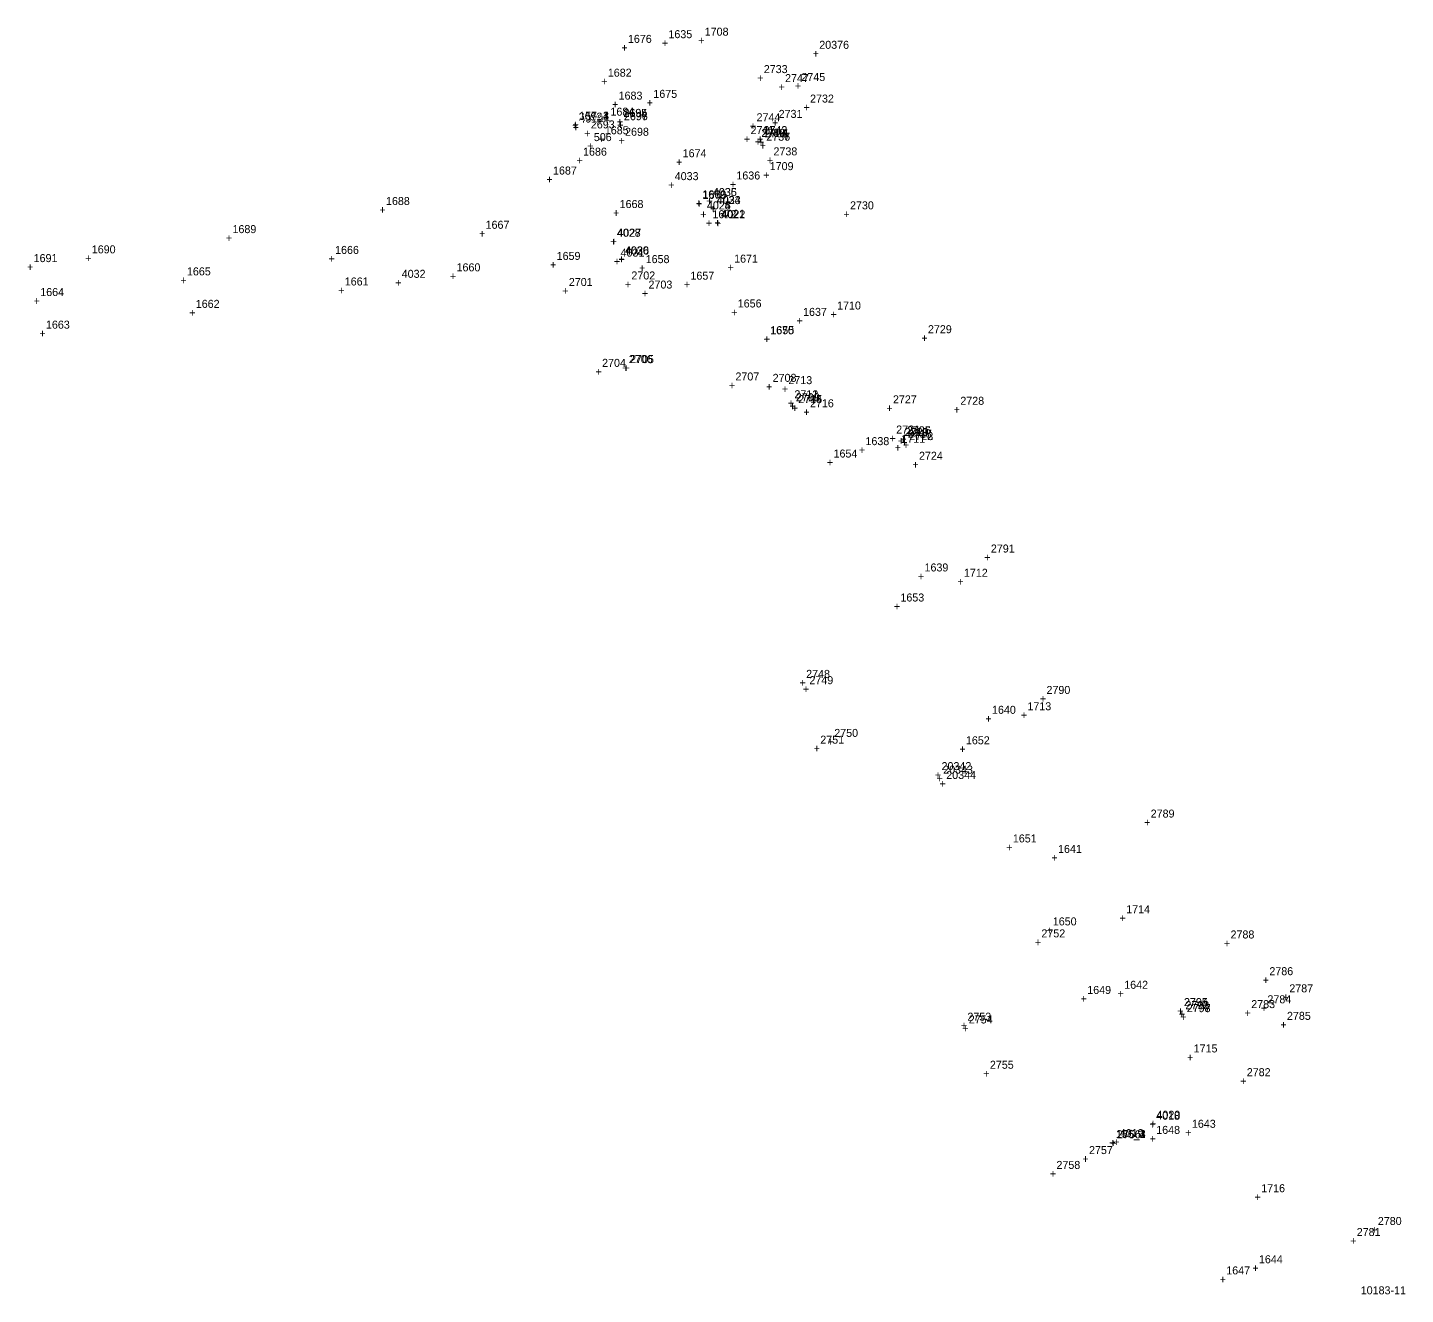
# Model space of a CAD drawing. Extents: x 1036751 to 1042192, y 772604 to 785439.
# Drawn here: x 1039355.7 to 1039786.2, y 776201.3 to 776597 of the extents above; entities that cross this region are included whole.
import ezdxf

# ---------------------------------------------------------------- set-up
doc = ezdxf.new("R2010")
doc.units = 0
for name, color, linetype in [('S_Buildings', 7, 'Continuous'), ('S_Buildings_SillElevation', 7, 'Continuous'), ('S_Control_Geodetic_ControlPoint', 7, 'Continuous'), ('S_Control_Temp_Traverse', 7, 'Continuous'), ('S_Control_Traverse_Point', 7, 'Continuous'), ('S_Drainage_CB', 7, 'Continuous'), ('S_Drainage_Culvert_Top', 7, 'Continuous'), ('S_Drainage_Invert', 7, 'Continuous'), ('S_Drainage_Sump', 7, 'Continuous'), ('S_Ground_LevelString', 7, 'Continuous'), ('S_Property_ElectricalOutlet', 7, 'Continuous'), ('S_Property_IronPipeFound', 7, 'Continuous'), ('S_Property_Mailbox', 7, 'Continuous'), ('S_Property_Well_Top', 7, 'Continuous'), ('S_Roadway_Centerline', 7, 'Continuous'), ('S_Roadway_Edge_Pavement', 7, 'Continuous'), ('S_Traffic_JunctionBox', 7, 'Continuous'), ('S_Traffic_Post_Conc', 7, 'Continuous'), ('S_Traffic_Sign_DoublePost', 7, 'Continuous'), ('S_Traffic_Sign_SinglePost', 7, 'Continuous'), ('S_Trees_Conifer_Pay', 7, 'Continuous'), ('S_Trees_Decid_Pay', 7, 'Continuous'), ('S_Trees_Stump', 7, 'Continuous'), ('S_Utilities_GuyWire3', 7, 'Continuous'), ('S_Utilities_Hydrant', 7, 'Continuous'), ('S_Utilities_Pole_Power', 7, 'Continuous'), ('S_Utilities_UG_Sanitary_MH', 7, 'Continuous'), ('S_Utilities_UG_Sanitary_Sewer', 7, 'Continuous'), ('S_Utilities_UG_Water_Gate', 7, 'Continuous'), ('S_Utilities_UG_Water_Line', 7, 'Continuous')]:
    doc.layers.add(name, color=color, linetype=linetype)

msp = doc.modelspace()

# ---------------------------------------------------------------- texts
at = {"layer": 'S_Buildings'}
for s, p in [('2704', (1039535.21, 776491.05)), ('+', (1039541.9, 776489.46)), ('2705', (1039543.96, 776492.21)), ('+', (1039533.15, 776488.3)), ('+', (1039596.9, 776391.15)), ('2748', (1039598.96, 776393.9)), ('2751', (1039603.37, 776373.35)), ('2750', (1039607.73, 776375.46)), ('+', (1039601.31, 776370.6)), ('+', (1039605.67, 776372.71)), ('2753', (1039649.32, 776286.82)), ('+', (1039647.26, 776284.07)), ('2755', (1039656.35, 776271.82)), ('+', (1039654.29, 776269.07))]:
    msp.add_text(s, height=2.5, dxfattribs=at).set_placement(p)
at = {"layer": 'S_Buildings_SillElevation'}
for s, p in [('+', (1039541.51, 776489.48)), ('2706', (1039543.57, 776492.23)), ('2749', (1039599.97, 776391.93)), ('+', (1039597.9, 776389.18)), ('+', (1039647.7, 776283.22)), ('2754', (1039649.76, 776285.97))]:
    msp.add_text(s, height=2.5, dxfattribs=at).set_placement(p)
at = {"layer": 'S_Control_Geodetic_ControlPoint'}
msp.add_text('10183-11', height=2.5, dxfattribs=at).set_placement((1039772.19, 776201.36))
msp.add_text('10183-11', height=2.5, dxfattribs=at).set_placement((1039772.19, 776201.36))
msp.add_text('10183-11', height=2.5, dxfattribs=at).set_placement((1039772.19, 776201.36))
msp.add_text('10183-11', height=2.5, dxfattribs=at).set_placement((1039772.19, 776201.36))
msp.add_text('10183-11', height=2.5, dxfattribs=at).set_placement((1039772.19, 776201.36))
msp.add_text('10183-11', height=2.5, dxfattribs=at).set_placement((1039772.19, 776201.36))
at = {"layer": 'S_Control_Temp_Traverse'}
for s, p in [('157_3', (1039528.05, 776568.25)), ('157_2', (1039528.05, 776568.25)), ('157', (1039528.05, 776568.25)), ('157', (1039528.05, 776568.25)), ('157_1', (1039528.05, 776568.25)), ('157_4', (1039528.05, 776568.25)), ('+', (1039525.99, 776565.5)), ('+', (1039525.99, 776565.5)), ('+', (1039525.99, 776565.5)), ('+', (1039525.99, 776565.5)), ('+', (1039525.99, 776565.5)), ('+', (1039525.99, 776565.5)), ('156', (1039695.7, 776250.22)), ('156_1', (1039695.7, 776250.22)), ('156_3', (1039695.7, 776250.22)), ('156_2', (1039695.7, 776250.22)), ('156_4', (1039695.7, 776250.22)), ('+', (1039693.64, 776247.47)), ('+', (1039693.64, 776247.47)), ('+', (1039693.64, 776247.47)), ('+', (1039693.64, 776247.47)), ('+', (1039693.64, 776247.47))]:
    msp.add_text(s, height=2.5, dxfattribs=at).set_placement(p)
at = {"layer": 'S_Control_Traverse_Point'}
for s, p in [('+', (1039530.56, 776558.82)), ('+', (1039530.56, 776558.82)), ('+', (1039530.56, 776558.82)), ('+', (1039530.56, 776558.82)), ('+', (1039530.56, 776558.82)), ('+', (1039530.56, 776558.82)), ('+', (1039530.56, 776558.82)), ('+', (1039530.56, 776558.82)), ('506', (1039532.62, 776561.57)), ('506', (1039532.62, 776561.57)), ('506', (1039532.62, 776561.57)), ('506', (1039532.62, 776561.57)), ('506', (1039532.62, 776561.57)), ('506', (1039532.62, 776561.57)), ('506', (1039532.62, 776561.57)), ('506', (1039532.62, 776561.57))]:
    msp.add_text(s, height=2.5, dxfattribs=at).set_placement(p)
at = {"layer": 'S_Drainage_CB'}
for s, p in [('2694', (1039541.93, 776569.13)), ('+', (1039539.86, 776566.38)), ('2734', (1039585.92, 776562.75)), ('+', (1039583.86, 776560)), ('2709', (1039595.76, 776480.33)), ('+', (1039593.7, 776477.58)), ('2717', (1039630.77, 776468.96)), ('+', (1039628.71, 776466.21)), ('+', (1039715.34, 776287.68)), ('2792', (1039717.4, 776290.43))]:
    msp.add_text(s, height=2.5, dxfattribs=at).set_placement(p)
at = {"layer": 'S_Drainage_Culvert_Top'}
for s, p in [('2697', (1039542.02, 776568.08)), ('2744', (1039583.46, 776567.76)), ('+', (1039539.96, 776565.33)), ('2698', (1039542.39, 776563.23)), ('+', (1039581.4, 776565.01)), ('2741', (1039581.58, 776563.73)), ('2740', (1039585, 776562.89)), ('2743', (1039585.66, 776563.7)), ('+', (1039540.33, 776560.48)), ('+', (1039579.52, 776560.98)), ('+', (1039582.93, 776560.14)), ('+', (1039583.6, 776560.95)), ('+', (1039584.44, 776558.92)), ('2737', (1039586.5, 776561.67)), ('+', (1039586.69, 776554.35)), ('2738', (1039588.75, 776557.1)), ('2713', (1039593.4, 776485.65)), ('+', (1039591.34, 776482.9)), ('2712', (1039595.28, 776481.23)), ('+', (1039593.22, 776478.48)), ('+', (1039594.47, 776476.97)), ('2715', (1039596.53, 776479.72)), ('2716', (1039600.15, 776478.42)), ('+', (1039624.01, 776476.9)), ('2727', (1039626.07, 776479.65)), ('+', (1039598.09, 776475.67)), ('2721', (1039627.08, 776470.22)), ('2720', (1039629.73, 776469.44)), ('2726', (1039630.41, 776469.99)), ('2723', (1039631.21, 776468.17)), ('+', (1039625.02, 776467.47)), ('+', (1039627.67, 776466.69)), ('+', (1039628.35, 776467.24)), ('+', (1039629.15, 776465.42)), ('+', (1039632.14, 776459.28)), ('2724', (1039634.2, 776462.03)), ('2795', (1039716.96, 776291.39)), ('+', (1039714.89, 776288.64)), ('2798', (1039717.83, 776289.5)), ('+', (1039715.77, 776286.75))]:
    msp.add_text(s, height=2.5, dxfattribs=at).set_placement(p)
at = {"layer": 'S_Drainage_Invert'}
for s, p in [('2696', (1039542.04, 776568.11)), ('+', (1039539.98, 776565.36)), ('2739', (1039584.96, 776562.9)), ('2742', (1039585.63, 776563.74)), ('+', (1039582.9, 776560.15)), ('+', (1039583.57, 776560.99)), ('+', (1039584.45, 776558.94)), ('2736', (1039586.51, 776561.69)), ('2711', (1039595.28, 776481.25)), ('+', (1039593.22, 776478.5)), ('+', (1039594.43, 776476.96)), ('2714', (1039596.49, 776479.71)), ('2719', (1039629.69, 776469.46)), ('2725', (1039630.44, 776469.97)), ('2722', (1039631.21, 776468.17)), ('+', (1039627.63, 776466.71)), ('+', (1039628.38, 776467.22)), ('+', (1039629.15, 776465.42)), ('2794', (1039716.99, 776291.38)), ('+', (1039714.93, 776288.63)), ('2797', (1039717.87, 776289.5)), ('+', (1039715.8, 776286.75))]:
    msp.add_text(s, height=2.5, dxfattribs=at).set_placement(p)
at = {"layer": 'S_Drainage_Sump'}
for s, p in [('2695', (1039541.85, 776569.12)), ('+', (1039539.79, 776566.37)), ('2735', (1039585.92, 776562.73)), ('+', (1039583.86, 776559.98)), ('+', (1039593.7, 776477.5)), ('2710', (1039595.76, 776480.25)), ('2718', (1039630.71, 776468.91)), ('+', (1039628.65, 776466.16)), ('+', (1039715.36, 776287.67)), ('2793', (1039717.42, 776290.42))]:
    msp.add_text(s, height=2.5, dxfattribs=at).set_placement(p)
at = {"layer": 'S_Ground_LevelString'}
for s, p in [('1676', (1039543.28, 776592.24)), ('+', (1039541.22, 776589.49)), ('1675', (1039551.22, 776575.07)), ('+', (1039549.16, 776572.32)), ('1674', (1039560.38, 776556.52)), ('+', (1039558.32, 776553.77)), ('1673', (1039566.61, 776543.51)), ('+', (1039564.55, 776540.76)), ('1672', (1039569.68, 776537.47)), ('+', (1039567.62, 776534.72)), ('1671', (1039576.46, 776523.59)), ('+', (1039574.4, 776520.84)), ('+', (1039585.64, 776498.46)), ('1670', (1039587.7, 776501.21))]:
    msp.add_text(s, height=2.5, dxfattribs=at).set_placement(p)
at = {"layer": 'S_Property_ElectricalOutlet'}
for s, p in [('2786', (1039743.65, 776301.04)), ('+', (1039741.58, 776298.29)), ('2785', (1039749.14, 776287.09)), ('+', (1039747.08, 776284.34))]:
    msp.add_text(s, height=2.5, dxfattribs=at).set_placement(p)
at = {"layer": 'S_Property_IronPipeFound'}
for s, p in [('2747', (1039592.37, 776579.98)), ('+', (1039590.3, 776577.23)), ('+', (1039704.52, 776347.52)), ('2789', (1039706.58, 776350.27))]:
    msp.add_text(s, height=2.5, dxfattribs=at).set_placement(p)
at = {"layer": 'S_Property_Mailbox'}
for s, p in [('+', (1039671.97, 776386.13)), ('2790', (1039674.03, 776388.88)), ('2752', (1039672.44, 776312.85)), ('+', (1039670.38, 776310.1))]:
    msp.add_text(s, height=2.5, dxfattribs=at).set_placement(p)
at = {"layer": 'S_Property_Well_Top'}
for s, p in [('2788', (1039731.52, 776312.51)), ('+', (1039729.45, 776309.76))]:
    msp.add_text(s, height=2.5, dxfattribs=at).set_placement(p)
at = {"layer": 'S_Roadway_Centerline'}
for s, p in [('1635', (1039555.93, 776593.71)), ('+', (1039553.87, 776590.96)), ('1636', (1039577.16, 776549.57)), ('+', (1039575.1, 776546.82)), ('1668', (1039540.69, 776540.65)), ('1669', (1039566.52, 776543.69)), ('+', (1039538.63, 776537.9)), ('+', (1039564.46, 776540.94)), ('1667', (1039498.82, 776534.18)), ('+', (1039496.76, 776531.43)), ('1666', (1039451.81, 776526.32)), ('1665', (1039405.53, 776519.62)), ('+', (1039449.75, 776523.57)), ('+', (1039403.46, 776516.87)), ('1664', (1039359.71, 776513.16)), ('+', (1039357.65, 776510.41)), ('1637', (1039597.99, 776506.97)), ('+', (1039595.93, 776504.22)), ('+', (1039615.42, 776463.85)), ('1638', (1039617.48, 776466.6)), ('1639', (1039635.93, 776427.15)), ('+', (1039633.87, 776424.4)), ('1640', (1039657.01, 776382.68)), ('+', (1039654.95, 776379.93)), ('1641', (1039677.63, 776339.22)), ('+', (1039675.57, 776336.47)), ('1642', (1039698.31, 776296.79)), ('+', (1039696.24, 776294.04)), ('1643', (1039719.45, 776253.38)), ('+', (1039717.39, 776250.63)), ('1644', (1039740.39, 776211.07)), ('+', (1039738.33, 776208.32))]:
    msp.add_text(s, height=2.5, dxfattribs=at).set_placement(p)
at = {"layer": 'S_Roadway_Edge_Pavement'}
for s, p in [('1708', (1039567.27, 776594.49)), ('+', (1039565.21, 776591.74)), ('1682', (1039537, 776581.68)), ('+', (1039534.94, 776578.93)), ('+', (1039538.31, 776571.77)), ('1683', (1039540.37, 776574.52)), ('1684', (1039537.82, 776569.5)), ('+', (1039535.76, 776566.75)), ('1685', (1039536.06, 776563.7)), ('+', (1039534, 776560.95)), ('+', (1039527.2, 776554.26)), ('1686', (1039529.26, 776557.01)), ('1687', (1039519.88, 776551.12)), ('+', (1039585.51, 776549.74)), ('1709', (1039587.57, 776552.49)), ('+', (1039517.82, 776548.37)), ('1688', (1039467.71, 776541.6)), ('+', (1039465.65, 776538.85)), ('1689', (1039419.76, 776532.82)), ('+', (1039417.69, 776530.07)), ('1691', (1039357.64, 776523.77)), ('1690', (1039375.81, 776526.5)), ('1659', (1039521.02, 776524.45)), ('1658', (1039548.83, 776523.45)), ('+', (1039355.58, 776521.02)), ('+', (1039373.75, 776523.75)), ('1660', (1039489.75, 776520.88)), ('+', (1039518.96, 776521.7)), ('+', (1039546.76, 776520.7)), ('1661', (1039454.83, 776516.47)), ('+', (1039487.69, 776518.13)), ('+', (1039560.75, 776515.53)), ('1657', (1039562.81, 776518.28)), ('+', (1039452.77, 776513.72)), ('+', (1039406.22, 776506.73)), ('1662', (1039408.29, 776509.48)), ('+', (1039575.53, 776506.85)), ('1656', (1039577.59, 776509.6)), ('1710', (1039608.62, 776508.96)), ('1663', (1039361.49, 776502.98)), ('+', (1039606.56, 776506.21)), ('+', (1039359.43, 776500.23)), ('+', (1039585.73, 776498.51)), ('1655', (1039587.79, 776501.26)), ('+', (1039626.63, 776464.58)), ('1711', (1039628.69, 776467.33)), ('+', (1039605.45, 776459.97)), ('1654', (1039607.51, 776462.72)), ('1712', (1039648.23, 776425.48)), ('+', (1039646.17, 776422.74)), ('1653', (1039628.4, 776417.76)), ('+', (1039626.34, 776415.01)), ('1713', (1039668.07, 776383.79)), ('+', (1039666.01, 776381.04)), ('1652', (1039648.86, 776373.16)), ('+', (1039646.8, 776370.41)), ('+', (1039661.45, 776339.76)), ('1651', (1039663.52, 776342.51)), ('+', (1039696.86, 776317.64)), ('1714', (1039698.93, 776320.39)), ('+', (1039673.94, 776313.84)), ('1650', (1039676, 776316.59)), ('+', (1039684.7, 776292.43)), ('1649', (1039686.76, 776295.18)), ('+', (1039717.93, 776274.17)), ('1715', (1039719.99, 776276.92)), ('+', (1039706.25, 776248.72)), ('1648', (1039708.31, 776251.47)), ('1716', (1039741.1, 776233.25)), ('+', (1039739.04, 776230.5)), ('1647', (1039730.18, 776207.58)), ('+', (1039728.12, 776204.83))]:
    msp.add_text(s, height=2.5, dxfattribs=at).set_placement(p)
at = {"layer": 'S_Traffic_JunctionBox'}
for s, p in [('2745', (1039597.47, 776580.33)), ('+', (1039595.41, 776577.58))]:
    msp.add_text(s, height=2.5, dxfattribs=at).set_placement(p)
at = {"layer": 'S_Traffic_Post_Conc'}
for s, p in [('2707', (1039576.86, 776486.8)), ('+', (1039574.8, 776484.05))]:
    msp.add_text(s, height=2.5, dxfattribs=at).set_placement(p)
at = {"layer": 'S_Traffic_Sign_DoublePost'}
for s, p in [('2784', (1039743.05, 776292.27)), ('+', (1039735.92, 776288.01)), ('2783', (1039737.98, 776290.76)), ('+', (1039740.98, 776289.52)), ('2780', (1039777.53, 776223.02)), ('2781', (1039770.94, 776219.57)), ('+', (1039775.47, 776220.27)), ('+', (1039768.88, 776216.82))]:
    msp.add_text(s, height=2.5, dxfattribs=at).set_placement(p)
at = {"layer": 'S_Traffic_Sign_SinglePost'}
for s, p in [('+', (1039529.64, 776562.77)), ('2693', (1039531.7, 776565.52)), ('+', (1039542.3, 776515.6)), ('2702', (1039544.36, 776518.35))]:
    msp.add_text(s, height=2.5, dxfattribs=at).set_placement(p)
at = {"layer": 'S_Trees_Conifer_Pay'}
for s, p in [('2787', (1039749.88, 776295.68)), ('+', (1039747.82, 776292.93))]:
    msp.add_text(s, height=2.5, dxfattribs=at).set_placement(p)
at = {"layer": 'S_Trees_Decid_Pay'}
for s, p in [('2701', (1039524.82, 776516.3)), ('2703', (1039549.71, 776515.5)), ('+', (1039522.76, 776513.55)), ('+', (1039547.65, 776512.75)), ('+', (1039634.94, 776498.81)), ('2729', (1039637, 776501.56)), ('2708', (1039588.49, 776486.37)), ('+', (1039586.43, 776483.62)), ('+', (1039645.05, 776476.45)), ('2728', (1039647.11, 776479.2))]:
    msp.add_text(s, height=2.5, dxfattribs=at).set_placement(p)
at = {"layer": 'S_Trees_Stump'}
for s, p in [('+', (1039610.6, 776537.5)), ('2730', (1039612.66, 776540.25))]:
    msp.add_text(s, height=2.5, dxfattribs=at).set_placement(p)
at = {"layer": 'S_Utilities_GuyWire3'}
for s, p in [('+', (1039583.66, 776580.05)), ('2733', (1039585.72, 776582.8)), ('2732', (1039600.18, 776573.6)), ('+', (1039598.12, 776570.85)), ('2758', (1039677.14, 776240.53)), ('+', (1039675.08, 776237.78))]:
    msp.add_text(s, height=2.5, dxfattribs=at).set_placement(p)
at = {"layer": 'S_Utilities_Hydrant'}
for s, p in [('2692', (1039527.87, 776567.94)), ('+', (1039525.81, 776565.19)), ('2756', (1039696.01, 776250.09)), ('+', (1039693.95, 776247.34))]:
    msp.add_text(s, height=2.5, dxfattribs=at).set_placement(p)
at = {"layer": 'S_Utilities_Pole_Power'}
for s, p in [('2731', (1039590.36, 776568.81)), ('+', (1039588.29, 776566.06)), ('2791', (1039656.66, 776433.06)), ('+', (1039654.6, 776430.31)), ('2782', (1039736.59, 776269.5)), ('+', (1039734.53, 776266.75)), ('2757', (1039687.31, 776245.17)), ('+', (1039685.24, 776242.42))]:
    msp.add_text(s, height=2.5, dxfattribs=at).set_placement(p)
at = {"layer": 'S_Utilities_UG_Sanitary_MH'}
for s, p in [('20376', (1039603.05, 776590.39)), ('+', (1039600.99, 776587.64)), ('20342', (1039641.25, 776365.09)), ('+', (1039639.18, 776362.34))]:
    msp.add_text(s, height=2.5, dxfattribs=at).set_placement(p)
at = {"layer": 'S_Utilities_UG_Sanitary_Sewer'}
for s, p in [('+', (1039639.7, 776361.24)), ('20343', (1039641.76, 776363.99)), ('20344', (1039642.72, 776362.33)), ('+', (1039640.65, 776359.58))]:
    msp.add_text(s, height=2.5, dxfattribs=at).set_placement(p)
at = {"layer": 'S_Utilities_UG_Water_Gate'}
for s, p in [('4033', (1039557.9, 776549.37)), ('+', (1039555.84, 776546.62)), ('+', (1039567.76, 776541.64)), ('4036', (1039569.82, 776544.39)), ('+', (1039565.9, 776537.47)), ('4025', (1039567.96, 776540.22)), ('4022', (1039572.51, 776537.42)), ('+', (1039570.45, 776534.67)), ('+', (1039537.76, 776528.93)), ('4028', (1039539.82, 776531.68))]:
    msp.add_text(s, height=2.5, dxfattribs=at).set_placement(p)
at = {"layer": 'S_Utilities_UG_Water_Line'}
for s, p in [('4029', (1039528.11, 776567.35)), ('+', (1039526.04, 776564.6)), ('+', (1039567.81, 776541.66)), ('4035', (1039569.87, 776544.41)), ('4034', (1039570.99, 776541.96)), ('4023', (1039571.06, 776541.88)), ('+', (1039565.88, 776537.48)), ('4024', (1039567.94, 776540.23)), ('+', (1039568.92, 776539.21)), ('+', (1039569, 776539.13)), ('4021', (1039572.36, 776537.6)), ('+', (1039570.3, 776534.85)), ('+', (1039537.92, 776528.95)), ('4027', (1039539.98, 776531.7)), ('4031', (1039540.98, 776525.48)), ('4030', (1039542.35, 776526.21)), ('4026', (1039542.44, 776526.12)), ('+', (1039538.92, 776522.73)), ('+', (1039540.29, 776523.46)), ('+', (1039540.37, 776523.37)), ('+', (1039470.56, 776516.11)), ('4032', (1039472.62, 776518.86)), ('+', (1039706.24, 776253.14)), ('+', (1039706.31, 776253.46)), ('4018', (1039708.3, 776255.89)), ('4020', (1039708.37, 776256.21)), ('4019', (1039696.9, 776250.46)), ('+', (1039694.84, 776247.71))]:
    msp.add_text(s, height=2.5, dxfattribs=at).set_placement(p)

doc.saveas('drawing.dxf')
